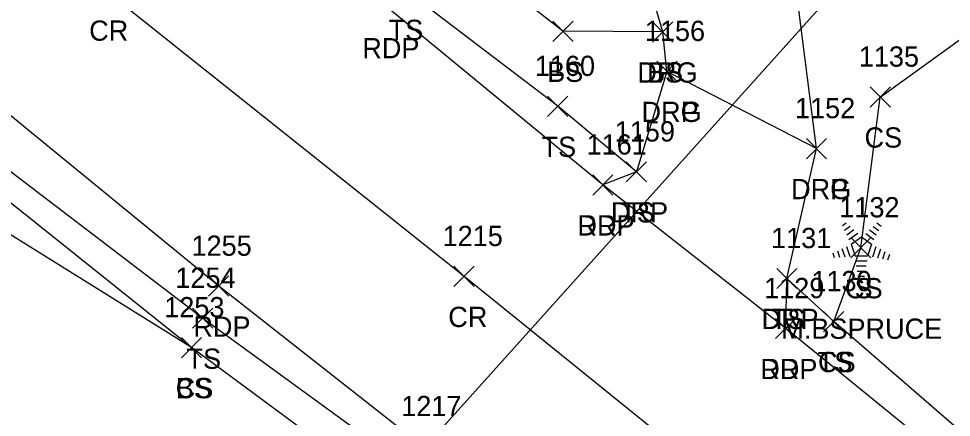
# Model space of a CAD drawing. Extents: x 1537342 to 1542195, y 163002 to 168596.
# Drawn here: x 1541938.8 to 1542030.9, y 163180.4 to 163219.8 of the extents above; entities that cross this region are included whole.
import ezdxf

# ---------------------------------------------------------------- set-up
doc = ezdxf.new("R2010")
doc.units = 0
for name, color, linetype in [('DCP', 7, 'Continuous'), ('L_A', 7, 'Continuous'), ('L_C', 7, 'Continuous'), ('L_I', 7, 'Continuous'), ('L_TIC', 7, 'Continuous'), ('LELB', 7, 'Continuous'), ('LTC', 7, 'Continuous'), ('P_A', 7, 'Continuous'), ('P_I', 7, 'Continuous'), ('P_TIC', 7, 'Continuous'), ('PET', 7, 'Continuous'), ('PRC', 7, 'Continuous'), ('R_A', 7, 'Continuous'), ('R_I', 7, 'Continuous'), ('R_TIC', 7, 'Continuous'), ('RDG', 7, 'Continuous'), ('RDP', 7, 'Continuous')]:
    doc.layers.add(name, color=color, linetype=linetype)

msp = doc.modelspace()

# ---------------------------------------------------------------- linework, layer by layer
at = {"layer": 'DCP'}
msp.add_lwpolyline([(1541974.927, 163172.921), (1542058.961, 163266.56)], dxfattribs=at)
at = {"layer": 'L_TIC'}
for points in [[(1541991.576, 163217.503), (1541993.576, 163219.503)], [(1541993.576, 163217.503), (1541991.576, 163219.503)], [(1542001.438, 163217.438), (1542003.438, 163219.438)], [(1542003.438, 163217.438), (1542001.438, 163219.438)], [(1542022.923, 163211.012), (1542024.923, 163213.012)], [(1542024.923, 163211.012), (1542022.923, 163213.012)], [(1541991.056, 163210.091), (1541993.056, 163212.091)], [(1541993.056, 163210.091), (1541991.056, 163212.091)], [(1541998.826, 163203.614), (1542000.826, 163205.614)], [(1542000.826, 163203.614), (1541998.826, 163205.614)], [(1542020.997, 163196.119), (1542022.997, 163198.119)], [(1542022.997, 163196.119), (1542020.997, 163198.119)], [(1542013.693, 163193.082), (1542015.693, 163195.082)], [(1542015.693, 163193.082), (1542013.693, 163195.082)], [(1541955.984, 163189.155), (1541957.984, 163191.155)], [(1541957.984, 163189.155), (1541955.984, 163191.155)], [(1542018.327, 163188.823), (1542020.327, 163190.823)], [(1542020.327, 163188.823), (1542018.327, 163190.823)], [(1542018.327, 163188.823), (1542020.327, 163190.823)], [(1542020.327, 163188.823), (1542018.327, 163190.823)], [(1541954.886, 163186.244), (1541956.886, 163188.244)], [(1541956.886, 163186.244), (1541954.886, 163188.244)], [(1541954.886, 163186.244), (1541956.886, 163188.244)], [(1541956.886, 163186.244), (1541954.886, 163188.244)]]:
    msp.add_lwpolyline(points, dxfattribs=at)
at = {"layer": 'LELB'}
for points in [[(1542002.438, 163218.438), (1541992.576, 163218.503), (1541981.665, 163227.078), (1541972.727, 163235.185), (1541952.245, 163252.94), (1541934.224, 163270.875), (1541926.758, 163276.805), (1541931.045, 163280.387), (1541930.665, 163296.396), (1541914.432, 163302.118), (1541899.504, 163302.033), (1541884.497, 163311.998), (1541872.596, 163319.595), (1541857.311, 163324.696)], [(1541981.521, 163166.612), (1541978.593, 163174.423), (1541956.984, 163190.155), (1541924.161, 163215.176), (1541866.464, 163254.002), (1541852.645, 163260.979), (1541835.078, 163274.973), (1541811.52, 163294.945), (1541800.604, 163304.36), (1541792.567, 163308.982)], [(1541955.886, 163187.244), (1541923.009, 163213.535), (1541863.649, 163251.537), (1541850.665, 163258.713), (1541835.078, 163274.973), (1541811.381, 163292.753), (1541797.026, 163303.082), (1541792.374, 163306.599)], [(1541982.352, 163154.541), (1541977.461, 163162.706), (1541976.488, 163171.882), (1541973.522, 163173.984), (1541972.191, 163175.206), (1541955.886, 163187.244), (1541919.334, 163210.017), (1541893.735, 163229.08), (1541863.644, 163247.964), (1541848.889, 163252.659), (1541830.956, 163271.76), (1541807.534, 163290.354), (1541793.299, 163299.343), (1541792.632, 163303.617)], [(1541999.826, 163204.614), (1541992.056, 163211.091), (1541976.951, 163222.645), (1541968.563, 163229.409), (1541948.761, 163245.023), (1541924.199, 163266.22), (1541916.662, 163273.43)], [(1542019.327, 163189.823), (1542021.997, 163197.119), (1542023.923, 163212.012), (1542033.032, 163218.579), (1542027.304, 163242.931), (1542014.56, 163249.195), (1542000.054, 163261.935), (1541997.358, 163271.883)], [(1542183.119, 163055.053), (1542146.295, 163085.373), (1542113.649, 163112.773), (1542073.54, 163147.501), (1542044.279, 163168.176), (1542019.327, 163189.823), (1542014.693, 163194.082)]]:
    msp.add_lwpolyline(points, dxfattribs=at)
at = {"layer": 'LTC'}
for p, q in [((1542020.193, 163199.327), (1542020.547, 163199.585)), ((1542020.402, 163198.862), (1542020.931, 163199.246)), ((1542023.22, 163199.22), (1542023.769, 163198.82)), ((1542023.591, 163199.568), (1542024.01, 163199.263)), ((1542020.612, 163198.396), (1542021.316, 163198.907)), ((1542020.821, 163197.93), (1542021.7, 163198.568)), ((1542021.046, 163197.475), (1542022.058, 163198.21)), ((1542022.058, 163198.21), (1542023.055, 163197.485)), ((1542022.478, 163198.523), (1542023.287, 163197.934)), ((1542022.849, 163198.871), (1542023.528, 163198.377)), ((1542020.591, 163197.256), (1542020.922, 163196.237)), ((1542021.046, 163197.475), (1542021.433, 163196.282)), ((1542023.055, 163197.485), (1542022.663, 163196.282)), ((1542019.225, 163196.607), (1542019.377, 163196.139)), ((1542019.681, 163196.823), (1542019.892, 163196.172)), ((1542020.136, 163197.04), (1542020.407, 163196.205)), ((1542023.492, 163197.214), (1542023.154, 163196.175)), ((1542023.937, 163196.964), (1542023.649, 163196.079)), ((1542024.381, 163196.714), (1542024.144, 163195.984)), ((1542024.826, 163196.463), (1542024.639, 163195.889)), ((1542022.663, 163196.282), (1542021.433, 163196.282)), ((1542022.625, 163195.782), (1542021.481, 163195.782)), ((1542022.541, 163195.282), (1542021.553, 163195.282)), ((1542022.458, 163194.782), (1542021.626, 163194.782)), ((1542022.374, 163194.282), (1542021.699, 163194.282))]:
    msp.add_line(p, q, dxfattribs=at)
at = {"layer": 'P_TIC'}
for points in [[(1541995.517, 163202.324), (1541997.517, 163204.324)], [(1541997.517, 163202.324), (1541995.517, 163204.324)], [(1541981.814, 163193.284), (1541983.814, 163195.284)], [(1541983.814, 163193.284), (1541981.814, 163195.284)], [(1541957.58, 163192.326), (1541959.58, 163194.326)], [(1541959.58, 163192.326), (1541957.58, 163194.326)], [(1542013.58, 163188.133), (1542015.58, 163190.133)], [(1542015.58, 163188.133), (1542013.58, 163190.133)]]:
    msp.add_lwpolyline(points, dxfattribs=at)
at = {"layer": 'PET'}
for points in [[(1542165.564, 163030.05), (1542126.673, 163058.359), (1542096.316, 163082.469), (1542058.609, 163112.541), (1542052.024, 163117.841), (1542010.734, 163151.352), (1541978.729, 163177.477), (1541958.58, 163193.326), (1541928.576, 163217.895), (1541894.651, 163244.61), (1541857.529, 163271.038), (1541839.599, 163283.446), (1541795.579, 163311.161), (1541814.195, 163318.824), (1541832.215, 163326.687)], [(1542182.456, 163052.966), (1542144.742, 163083.141), (1542111.589, 163110.066), (1542069.863, 163143.449), (1542042.929, 163166.036), (1542014.58, 163189.133), (1541996.517, 163203.324), (1541975.27, 163220.837), (1541953.956, 163238.227), (1541914.853, 163268.66), (1541894.388, 163284.999), (1541874.186, 163298.085), (1541854.833, 163311.466), (1541832.215, 163326.687)]]:
    msp.add_lwpolyline(points, dxfattribs=at)
at = {"layer": 'PRC'}
msp.add_lwpolyline([(1542174.182, 163041.839), (1542135.376, 163070.507), (1542102.151, 163097.417), (1542058.019, 163132.978), (1542032.763, 163153.879), (1541982.814, 163194.284), (1541947.346, 163222.574), (1541904.323, 163256.107), (1541874.287, 163278.529), (1541825.993, 163311.002), (1541814.195, 163318.824)], dxfattribs=at)
at = {"layer": 'R_TIC'}
for points in [[(1542001.438, 163217.438), (1542003.438, 163219.438)], [(1542003.438, 163217.438), (1542001.438, 163219.438)], [(1542001.848, 163213.546), (1542003.848, 163215.546)], [(1542003.848, 163213.546), (1542001.848, 163215.546)], [(1542001.848, 163213.546), (1542003.848, 163215.546)], [(1542003.848, 163213.546), (1542001.848, 163215.546)], [(1542016.62, 163205.917), (1542018.62, 163207.917)], [(1542018.62, 163205.917), (1542016.62, 163207.917)], [(1542016.62, 163205.917), (1542018.62, 163207.917)], [(1542018.62, 163205.917), (1542016.62, 163207.917)], [(1541998.826, 163203.614), (1542000.826, 163205.614)], [(1542000.826, 163203.614), (1541998.826, 163205.614)], [(1541995.517, 163202.324), (1541997.517, 163204.324)], [(1541997.517, 163202.324), (1541995.517, 163204.324)], [(1542013.693, 163193.082), (1542015.693, 163195.082)], [(1542015.693, 163193.082), (1542013.693, 163195.082)], [(1542013.58, 163188.133), (1542015.58, 163190.133)], [(1542015.58, 163188.133), (1542013.58, 163190.133)]]:
    msp.add_lwpolyline(points, dxfattribs=at)
at = {"layer": 'RDG'}
for points in [[(1542017.62, 163206.917), (1542015.196, 163226.11), (1542009.877, 163243.692), (1541994.503, 163258.921), (1541988.515, 163265.136), (1541982.386, 163272.123), (1541977.907, 163278.251), (1541973.34, 163281.582), (1541963.148, 163285.487), (1541948.659, 163292.511), (1541930.665, 163296.396), (1541918.384, 163296.027), (1541913.61, 163296.24), (1541903.895, 163289.032)], [(1542002.848, 163214.546), (1542002.438, 163218.438), (1541997.038, 163236.795), (1541985.193, 163249.902), (1541958.701, 163267.577), (1541939.931, 163277.382), (1541931.045, 163280.387), (1541922.489, 163280.521), (1541918.32, 163277.033)]]:
    msp.add_lwpolyline(points, dxfattribs=at)
at = {"layer": 'RDP'}
msp.add_lwpolyline([(1542014.58, 163189.133), (1542014.693, 163194.082), (1542017.62, 163206.917), (1542002.848, 163214.546), (1541999.826, 163204.614), (1541996.517, 163203.324)], dxfattribs=at)

# ---------------------------------------------------------------- texts
at = {"layer": 'L_A'}
for s, p in [('TS', (1541975.36, 163217.645)), ('BS', (1541991.017, 163213.503)), ('BS', (1542000.879, 163213.438)), ('CS', (1542022.364, 163207.012)), ('TS', (1541990.465, 163206.091)), ('TS', (1541998.236, 163199.614)), ('CS', (1542020.438, 163192.119)), ('S', (1542021.383, 163192.119)), ('TS', (1542013.102, 163189.082)), ('TS', (1541955.394, 163185.155)), ('TS', (1542017.737, 163184.823)), ('CS', (1542017.768, 163184.823)), ('CS', (1541954.327, 163182.244)), ('BS', (1541954.327, 163182.244))]:
    msp.add_text(s, height=2, dxfattribs=at).set_placement(p)
at = {"layer": 'L_C'}
msp.add_text('M.BSPRUCE', height=2, dxfattribs=at).set_placement((1542014.139, 163188.119))
at = {"layer": 'L_I'}
for s, p in [('1135', (1542021.797, 163215.012)), ('1160', (1541989.796, 163214.091)), ('1159', (1541997.693, 163207.614)), ('1132', (1542019.872, 163200.119)), ('1132', (1542019.872, 163200.119)), ('1131', (1542013.134, 163197.082)), ('1254', (1541954.292, 163193.155)), ('1130', (1542017.115, 163192.823)), ('1130', (1542017.115, 163192.823)), ('1253', (1541953.194, 163190.244)), ('1253', (1541953.194, 163190.244))]:
    msp.add_text(s, height=2, dxfattribs=at).set_placement(p)
at = {"layer": 'LTC'}
msp.add_text('.', height=1.037, rotation=270, dxfattribs=at).set_placement((1542021.94, 163197.223))
at = {"layer": 'P_A'}
for s, p in [('CR', (1541945.779, 163217.574)), ('RDP', (1541972.758, 163215.837)), ('RDP', (1541994.005, 163198.324)), ('CR', (1541981.247, 163189.284)), ('RDP', (1541956.069, 163188.326)), ('RDP', (1542012.068, 163184.133))]:
    msp.add_text(s, height=2, dxfattribs=at).set_placement(p)
at = {"layer": 'P_I'}
for s, p in [('1161', (1541994.911, 163206.324)), ('1215', (1541980.688, 163197.284)), ('1255', (1541955.888, 163196.326)), ('1129', (1542012.446, 163192.133)), ('1217', (1541976.604, 163180.477)), ('1217', (1541976.604, 163180.477))]:
    msp.add_text(s, height=2, dxfattribs=at).set_placement(p)
at = {"layer": 'R_A'}
for s, p in [('DRG', (1541999.926, 163213.438)), ('DRG', (1542000.336, 163209.546)), ('DRP', (1542000.336, 163209.546)), ('DRG', (1542015.109, 163201.917)), ('DRP', (1542015.109, 163201.917)), ('DRP', (1541997.314, 163199.614)), ('DRP', (1541994.005, 163198.324)), ('DRP', (1542012.181, 163189.082)), ('DRP', (1542012.068, 163184.133))]:
    msp.add_text(s, height=2, dxfattribs=at).set_placement(p)
at = {"layer": 'R_I'}
for s, p in [('1156', (1542000.667, 163217.546)), ('1156', (1542000.667, 163217.546)), ('1152', (1542015.495, 163209.917)), ('1152', (1542015.495, 163209.917)), ('1159', (1541997.693, 163207.614)), ('1161', (1541994.911, 163206.324)), ('1131', (1542013.134, 163197.082)), ('1129', (1542012.446, 163192.133))]:
    msp.add_text(s, height=2, dxfattribs=at).set_placement(p)

doc.saveas('drawing.dxf')
